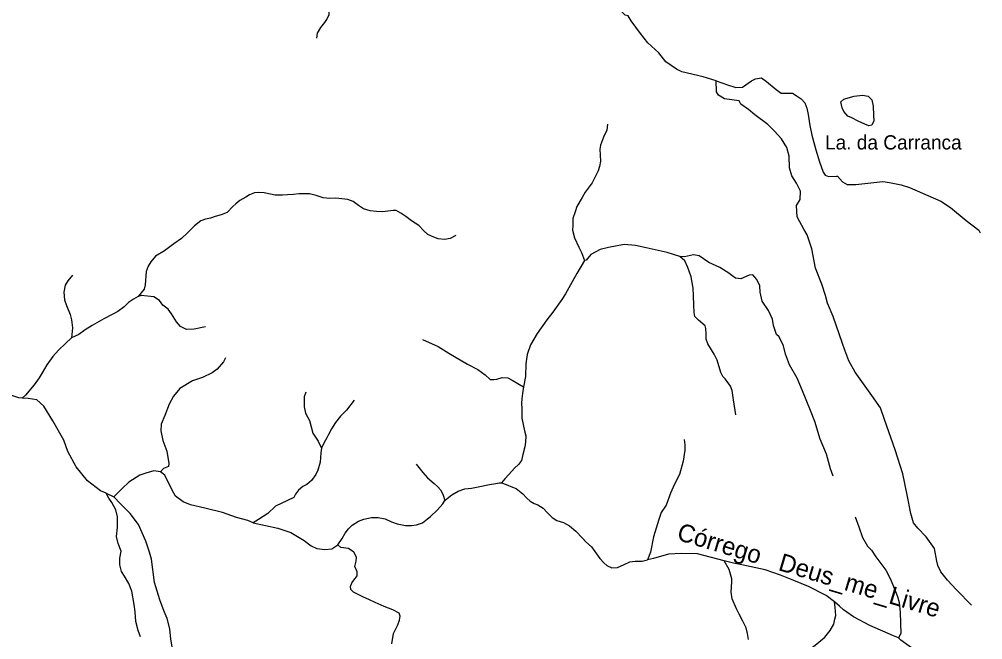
# Model space of a CAD drawing. Extents: x 717.8 to 772.7, y 8672.2 to 8728.
# Drawn here: x 761.61 to 772.42, y 8693.87 to 8700.84 of the extents above; entities that cross this region are included whole.
import ezdxf
from ezdxf.enums import TextEntityAlignment as Align

# ---------------------------------------------------------------- set-up
doc = ezdxf.new("R2010")
doc.units = 0
doc.header["$LTSCALE"] = 0.08
doc.linetypes.add('LONG_DASHED', pattern=[7.5, 6, -1.5])
doc.layers.add('3', color=7, linetype='LONG_DASHED', lineweight=25)
doc.layers.add('9', color=7, linetype='LONG_DASHED', lineweight=25)
doc.layers.add('61', color=7, linetype='Continuous')

msp = doc.modelspace()

# ---------------------------------------------------------------- linework, layer by layer
at = {"layer": '3'}
for points in [[(770.8462, 8699.8467), (770.829, 8699.9124), (770.8634, 8699.9428), (770.8867, 8699.9503)], [(770.8867, 8699.9503), (770.9788, 8699.9778), (771.0726, 8699.9883), (771.1373, 8699.9782), (771.1778, 8699.9367), (771.1938, 8699.8654), (771.1968, 8699.765), (771.1998, 8699.701), (771.1798, 8699.6515), (771.1443, 8699.6432), (771.1014, 8699.6614), (771.0245, 8699.6979), (770.954, 8699.7343), (770.9079, 8699.7526), (770.865, 8699.8042), (770.8462, 8699.8467)]]:
    msp.add_lwpolyline(points, dxfattribs=at)
at = {"layer": '9'}
msp.add_line((762.5827, 8695.5157), (762.6703, 8695.4765), dxfattribs=at)
for points in [[(764.9492, 8700.6283), (764.9568, 8700.6836), (764.9933, 8700.7489), (765.0358, 8700.8045), (765.0603, 8700.8374), (765.0866, 8700.8944), (765.0806, 8701.0439), (765.067, 8701.0857), (765.0496, 8701.173), (765.0526, 8701.2747), (765.0843, 8701.3926), (765.1202, 8701.4825), (765.1866, 8701.7016), (765.2041, 8701.7251)], [(769.4305, 8700.1491), (769.2842, 8700.1939), (769.0451, 8700.2496), (768.9852, 8700.279), (768.8659, 8700.3643), (768.7872, 8700.4645), (768.6633, 8700.5745), (768.5828, 8700.6794), (768.4757, 8700.8226), (768.4437, 8700.8809), (768.4086, 8700.8887), (768.3161, 8700.9848), (768.2855, 8701.014)], [(769.4305, 8700.1491), (769.5579, 8700.1036), (769.6531, 8700.0755), (769.7281, 8700.0798), (769.8284, 8700.1505), (769.8731, 8700.1736), (769.9408, 8700.1816), (769.9971, 8700.1426), (770.1024, 8700.0532), (770.1601, 8700.0121), (770.2858, 8700.0126), (770.3297, 8699.9852)], [(772.2973, 8694.2594), (772.13, 8694.4311), (772.0272, 8694.5392), (771.9522, 8694.6337), (771.919, 8694.703), (771.9082, 8694.7535), (771.8824, 8694.8934), (771.7892, 8695.0275), (771.6933, 8695.122), (771.6457, 8695.1833), (771.6153, 8695.2889), (771.576, 8695.4992), (771.5276, 8695.7351), (771.4394, 8696.0051), (771.3195, 8696.3431), (771.2741, 8696.4751), (771.1767, 8696.6157), (770.9899, 8696.8769), (770.9213, 8697.0039), (770.8745, 8697.1243), (770.8471, 8697.1964), (770.7434, 8697.5002), (770.6814, 8697.6496), (770.6576, 8697.7369), (770.618, 8697.8646), (770.5451, 8698.0456), (770.5055, 8698.2605), (770.4523, 8698.4193), (770.4162, 8698.4842), (770.3693, 8698.5636), (770.3398, 8698.6206), (770.3341, 8698.7469), (770.3723, 8698.8176), (770.3774, 8698.9106), (770.3341, 8698.9979), (770.2807, 8699.083), (770.2543, 8699.171), (770.2514, 8699.3023), (770.2248, 8699.4004), (770.1627, 8699.497), (770.0842, 8699.5857), (770.0106, 8699.6599), (769.8643, 8699.7689), (769.7929, 8699.8258), (769.709, 8699.8871), (769.6879, 8699.9243), (769.5232, 8699.9488), (769.4564, 8699.9877), (769.4353, 8700.024), (769.4305, 8700.1491)], [(770.3297, 8699.9852), (770.3845, 8699.9457), (770.4249, 8699.9023), (770.4502, 8699.8417), (770.4624, 8699.7724), (770.4828, 8699.6479), (770.5046, 8699.5389), (770.5513, 8699.3743)], [(768.2115, 8699.6608), (768.2024, 8699.5959), (768.1649, 8699.5164), (768.1323, 8699.4277), (768.1239, 8699.3822), (768.1323, 8699.2485), (768.1206, 8699.1881), (768.1051, 8699.1368), (768.0733, 8699.0699), (768.0371, 8699.0046), (767.9596, 8698.8984), (767.9252, 8698.8367), (767.8649, 8698.736), (767.8461, 8698.6763), (767.8206, 8698.6034), (767.8204, 8698.5223), (767.8161, 8698.471), (767.8407, 8698.3859), (767.8901, 8698.282), (767.9201, 8698.2206), (767.9528, 8698.1295)], [(770.5513, 8699.3743), (770.5903, 8699.2401), (770.6302, 8699.1242), (770.6525, 8699.0907), (770.6935, 8699.0748), (770.7802, 8699.08), (770.7931, 8699.0792), (770.8494, 8699.015), (770.9006, 8698.9833), (770.9979, 8698.9847), (771.3001, 8699.0201), (771.3754, 8699.0061), (771.5059, 8698.9825), (771.6026, 8698.9521), (771.9525, 8698.7968), (772.0603, 8698.727), (772.237, 8698.5818), (772.3809, 8698.4704), (772.3933, 8698.4434)], [(766.5089, 8698.4106), (766.4463, 8698.376), (766.3791, 8698.3676), (766.311, 8698.3742), (766.2624, 8698.3919), (766.1952, 8698.4246), (766.1486, 8698.4657), (766.0944, 8698.5236), (766.0105, 8698.5759), (765.9484, 8698.6237), (765.8925, 8698.6612), (765.8388, 8698.6908), (765.8033, 8698.6917), (765.7455, 8698.6861), (765.6849, 8698.6774), (765.6172, 8698.6821), (765.5473, 8698.6891), (765.4702, 8698.7124), (765.4169, 8698.7487), (765.3562, 8698.7926), (765.2942, 8698.8177), (765.2266, 8698.8248), (765.1612, 8698.8294), (765.0931, 8698.8291), (765.0194, 8698.8338), (764.942, 8698.8622), (764.865, 8698.8786), (764.7506, 8698.8795), (764.685, 8698.8741), (764.6198, 8698.8695), (764.563, 8698.8645), (764.4789, 8698.8665), (764.4277, 8698.8762), (764.3555, 8698.8927), (764.2948, 8698.895), (764.2481, 8698.8927), (764.1899, 8698.8669), (764.1502, 8698.8435), (764.0849, 8698.8061), (764.0382, 8698.7687), (764.0033, 8698.7383), (763.9404, 8698.6704), (763.8751, 8698.6447), (763.8075, 8698.6237), (763.7538, 8698.6073), (763.6979, 8698.5957), (763.6454, 8698.5746), (763.5746, 8698.5193), (763.499, 8698.4436), (763.4271, 8698.3783), (763.3412, 8698.3166), (763.2375, 8698.2379), (763.1349, 8698.1812), (763.0852, 8698.1156), (763.0543, 8698.0659), (763.0311, 8698.0088), (763.0264, 8697.9573), (763.0241, 8697.9058), (763.0218, 8697.8566), (763.0102, 8697.8098), (762.9437, 8697.7266)], [(769.0237, 8698.1752), (768.8804, 8698.2221), (768.6466, 8698.2723), (768.5246, 8698.2987), (768.3975, 8698.3113), (768.2202, 8698.2783), (768.1283, 8698.2548), (768.0248, 8698.1971), (767.9723, 8698.1359), (767.9528, 8698.1295)], [(770.7448, 8695.7086), (770.7131, 8695.7881), (770.6711, 8695.9537), (770.5986, 8696.122), (770.539, 8696.322), (770.4906, 8696.4435), (770.4003, 8696.6674), (770.3386, 8696.8102), (770.2553, 8696.9575), (770.2098, 8697.0779), (770.1849, 8697.1726), (770.1388, 8697.2738), (770.1087, 8697.2993), (770.0748, 8697.3989), (770.0624, 8697.4707), (770.0185, 8697.5686), (769.946, 8697.6743), (769.9234, 8697.7765), (769.9199, 8697.8464), (769.889, 8697.9189), (769.842, 8697.9683), (769.8011, 8697.9675), (769.7061, 8697.9251), (769.6467, 8697.9328), (769.6081, 8697.9621), (769.5744, 8697.9882), (769.4704, 8698.052), (769.3477, 8698.1098), (769.2392, 8698.1843), (769.1766, 8698.1931), (769.0745, 8698.1716), (769.0237, 8698.1752)], [(767.9528, 8698.1295), (767.8647, 8697.9862), (767.8125, 8697.8897), (767.7379, 8697.7561), (767.6978, 8697.6941), (767.5982, 8697.549), (767.5307, 8697.4643), (767.4227, 8697.3088), (767.3474, 8697.1825), (767.3105, 8697.075), (767.2933, 8696.9715), (767.29, 8696.8257), (767.2672, 8696.7098)], [(769.6513, 8696.3983), (769.6262, 8696.5653), (769.611, 8696.6712), (769.5913, 8696.7192), (769.5553, 8696.7716), (769.5307, 8696.8029), (769.5058, 8696.8291), (769.4814, 8696.872), (769.4434, 8697.0105), (769.4099, 8697.0783), (769.3369, 8697.196), (769.3181, 8697.2466), (769.3189, 8697.3085), (769.3146, 8697.3677), (769.3053, 8697.3982), (769.2323, 8697.4586), (769.1902, 8697.4999), (769.1833, 8697.5462), (769.1816, 8697.6278), (769.1773, 8697.7386), (769.173, 8697.8206), (769.1487, 8697.9489), (769.1143, 8698.0505), (769.0778, 8698.1285), (769.0237, 8698.1752)], [(762.2035, 8697.967), (762.1511, 8697.9032), (762.1229, 8697.8526), (762.1079, 8697.7757), (762.1132, 8697.6889), (762.1389, 8697.6256), (762.1785, 8697.5226), (762.1948, 8697.4641), (762.2065, 8697.3752), (762.1948, 8697.2628)], [(762.9437, 8697.7266), (762.8913, 8697.6953), (762.8329, 8697.6603), (762.784, 8697.6112), (762.7142, 8697.5567), (762.6496, 8697.5239), (762.5577, 8697.4735), (762.426, 8697.3988), (762.3467, 8697.3522), (762.2744, 8697.3008), (762.1948, 8697.2628)], [(763.6982, 8697.384), (763.5712, 8697.3587), (763.4835, 8697.3569), (763.4181, 8697.3886), (763.3733, 8697.4428), (763.3164, 8697.5296), (763.28, 8697.5829), (763.2202, 8697.6277), (763.1818, 8697.6795), (763.1163, 8697.722), (762.9753, 8697.7371), (762.9437, 8697.7266)], [(762.1948, 8697.2628), (762.1274, 8697.1982), (762.0481, 8697.1235), (761.9851, 8697.0533), (761.9174, 8696.9602), (761.8632, 8696.8668), (761.8315, 8696.8106), (761.7734, 8696.7347), (761.676, 8696.6184), (761.6383, 8696.5849)], [(766.1343, 8697.242), (766.3086, 8697.1636), (766.4301, 8697.0901), (766.6375, 8696.9643), (766.7554, 8696.9068), (766.8372, 8696.8445), (766.8947, 8696.7949), (766.9331, 8696.7929), (766.9665, 8696.7959), (767.0295, 8696.815), (767.0918, 8696.8105), (767.1409, 8696.7874), (767.2027, 8696.7486), (767.2672, 8696.7098)], [(763.921, 8697.0363), (763.9014, 8696.9915), (763.8298, 8696.9104), (763.7717, 8696.8698), (763.6643, 8696.8157), (763.5523, 8696.7786), (763.409, 8696.6931), (763.3401, 8696.6071), (763.2882, 8696.5183), (763.2426, 8696.391), (763.2004, 8696.2899), (763.1959, 8696.217), (763.217, 8696.1088), (763.2626, 8695.9887), (763.2855, 8695.8492), (763.2812, 8695.8153), (763.2279, 8695.7934), (763.1917, 8695.7552)], [(761.6383, 8696.5849), (761.6018, 8696.5876), (761.4904, 8696.6249), (761.4087, 8696.6621), (761.2158, 8696.6625), (761.1192, 8696.6849), (760.9494, 8696.7388), (760.9022, 8696.7484)], [(767.2672, 8696.7098), (767.2569, 8696.6348), (767.249, 8696.5779), (767.2465, 8696.5236), (767.249, 8696.4694), (767.249, 8696.4202), (767.2489, 8696.3607), (767.2654, 8696.2888), (767.2782, 8696.2157), (767.2941, 8696.1616), (767.2916, 8696.0891), (767.2838, 8696.0374), (767.2619, 8695.9495), (767.2438, 8695.8822), (767.2124, 8695.8368), (767.1678, 8695.7967), (767.1034, 8695.7268), (767.0597, 8695.6776), (767.0204, 8695.6324)], [(762.5827, 8695.5157), (762.5209, 8695.5421), (762.3748, 8695.6561), (762.2441, 8695.814), (762.1526, 8695.9848), (762.1066, 8696.1124), (761.9828, 8696.3302), (761.8844, 8696.4953), (761.8026, 8696.5655), (761.7057, 8696.58), (761.6383, 8696.5849)], [(764.8248, 8696.6496), (764.8062, 8696.5996), (764.804, 8696.4863), (764.821, 8696.4138), (764.8671, 8696.3319), (764.9045, 8696.1893), (764.9632, 8696.1004), (765, 8696.0208)], [(765.3684, 8696.5627), (765.2802, 8696.4508), (765.2129, 8696.3807), (765.1588, 8696.3122), (765.112, 8696.2408), (765.0779, 8696.1751), (765.0616, 8696.1376), (765.0288, 8696.085), (765, 8696.0208)], [(769.0697, 8696.1212), (769.0788, 8696.0585), (769.0789, 8695.9981), (769.062, 8695.8769), (769.0201, 8695.7256), (768.9613, 8695.6163), (768.9194, 8695.5154), (768.8675, 8695.3798), (768.8129, 8695.2999), (768.7853, 8695.221), (768.7268, 8695.0276), (768.6939, 8694.853), (768.6602, 8694.767)], [(765, 8696.0208), (764.9926, 8695.9691), (764.9862, 8695.8661), (764.958, 8695.7733), (764.9351, 8695.7249), (764.8891, 8695.6586), (764.8351, 8695.6134), (764.7919, 8695.5897), (764.7415, 8695.55), (764.7081, 8695.5041), (764.6896, 8695.4686), (764.6186, 8695.434), (764.4835, 8695.3716), (764.3964, 8695.2882), (764.2924, 8695.2192), (764.233, 8695.1823)], [(766.0634, 8695.8442), (766.136, 8695.7477), (766.1902, 8695.69), (766.2637, 8695.6239), (766.3051, 8695.5877), (766.3373, 8695.5532), (766.3606, 8695.5066), (766.3837, 8695.435)], [(763.1917, 8695.7552), (763.1187, 8695.7663), (763.0285, 8695.7408), (762.9602, 8695.7174), (762.8379, 8695.6385)], [(764.233, 8695.1823), (764.1746, 8695.208), (764.0474, 8695.2444), (763.8899, 8695.299), (763.6898, 8695.3483), (763.529, 8695.387), (763.4489, 8695.4175), (763.3623, 8695.4834), (763.3234, 8695.5504), (763.2429, 8695.7169), (763.1917, 8695.7552)], [(762.8379, 8695.6385), (762.7601, 8695.5641), (762.6703, 8695.4765)], [(766.3837, 8695.435), (766.4118, 8695.4553), (766.4638, 8695.499), (766.5356, 8695.5391), (766.6076, 8695.5661), (766.685, 8695.5738), (766.7576, 8695.5894), (766.8845, 8695.6142), (766.9589, 8695.6253), (766.9929, 8695.6324), (767.0204, 8695.6324)], [(767.0204, 8695.6324), (767.0726, 8695.6135), (767.1448, 8695.5851), (767.1864, 8695.5679), (767.2615, 8695.5101), (767.3029, 8695.4629), (767.341, 8695.425), (767.3867, 8695.4002), (767.4291, 8695.3853), (767.4884, 8695.3482), (767.5341, 8695.2976), (767.5905, 8695.2442), (767.6401, 8695.2085), (767.7162, 8695.1855), (767.7855, 8695.1498), (767.8568, 8695.0901), (767.929, 8695.0096), (767.9676, 8694.9711), (768.0302, 8694.9145), (768.1251, 8694.7837), (768.1703, 8694.7341), (768.2031, 8694.7022), (768.2609, 8694.6762), (768.3244, 8694.681), (768.3971, 8694.7151), (768.4627, 8694.7446), (768.52, 8694.7537), (768.6, 8694.7518), (768.6602, 8694.767)], [(762.9672, 8693.9006), (762.9407, 8693.9735), (762.9154, 8694.0754), (762.9093, 8694.1819), (762.8984, 8694.2645), (762.8712, 8694.4169), (762.8385, 8694.5008), (762.7876, 8694.5823), (762.7561, 8694.637), (762.735, 8694.7119), (762.7367, 8694.7858), (762.7492, 8694.863), (762.719, 8694.9503), (762.6978, 8695.0303), (762.7086, 8695.1362), (762.7103, 8695.2495), (762.69, 8695.329), (762.6468, 8695.4127), (762.6113, 8695.4618), (762.5827, 8695.5157)], [(763.3248, 8693.7917), (763.3081, 8693.8752), (763.2957, 8693.993), (763.2668, 8694.1079), (763.234, 8694.1876), (763.1865, 8694.3198), (763.1266, 8694.5109), (763.0905, 8694.7741), (763.0701, 8694.8529), (763.0284, 8694.9772), (762.9453, 8695.164), (762.8514, 8695.2867), (762.7437, 8695.3978), (762.6703, 8695.4765)], [(765.1848, 8694.937), (765.232, 8695.0068), (765.2663, 8695.0677), (765.3016, 8695.1153), (765.346, 8695.1586), (765.4154, 8695.2003), (765.4771, 8695.2239), (765.5622, 8695.2447), (765.6371, 8695.2422), (765.7144, 8695.2267), (765.7867, 8695.1958), (765.8513, 8695.1726), (765.9442, 8695.1545), (766.0114, 8695.152), (766.0681, 8695.1599), (766.1326, 8695.1832), (766.1918, 8695.2271), (766.2234, 8695.2539), (766.3033, 8695.3303), (766.3612, 8695.3974), (766.3837, 8695.435)], [(764.233, 8695.1823), (764.5104, 8695.1223), (764.6558, 8695.076), (764.8068, 8694.9853), (764.8837, 8694.925), (764.9486, 8694.8954), (765.0393, 8694.8824), (765.1144, 8694.8917), (765.1848, 8694.937)], [(770.9902, 8695.2495), (771.0332, 8695.1384), (771.0747, 8695.0192), (771.1289, 8694.9219), (771.1746, 8694.8763), (771.2227, 8694.8002), (771.3345, 8694.65), (771.3881, 8694.5514), (771.4304, 8694.4501), (771.4674, 8694.3541), (771.4853, 8694.2893), (771.4965, 8694.1754), (771.503, 8693.9387), (771.4783, 8693.8903)], [(765.7901, 8693.8225), (765.8094, 8693.9386), (765.8307, 8693.9857), (765.8561, 8694.0371), (765.8746, 8694.0904), (765.883, 8694.1342), (765.8701, 8694.1678), (765.7994, 8694.2054), (765.7023, 8694.2425), (765.6011, 8694.2883), (765.5377, 8694.3187), (765.4659, 8694.3534), (765.4104, 8694.3775), (765.3599, 8694.4045), (765.3291, 8694.4359), (765.3247, 8694.4683), (765.3399, 8694.5104), (765.3774, 8694.557), (765.3999, 8694.589), (765.401, 8694.6322), (765.3735, 8694.6911), (765.3874, 8694.7517), (765.3917, 8694.7957), (765.3643, 8694.8534), (765.3023, 8694.893), (765.217, 8694.9077), (765.1848, 8694.937)], [(769.5198, 8694.7559), (769.221, 8694.8356), (769.0423, 8694.8404), (768.8959, 8694.8322), (768.7267, 8694.7807), (768.6602, 8694.767)], [(769.7929, 8693.8715), (769.7813, 8693.9413), (769.7673, 8694.0029), (769.7283, 8694.0784), (769.6886, 8694.1571), (769.6595, 8694.2174), (769.6108, 8694.3284), (769.6004, 8694.4058), (769.6051, 8694.5196), (769.605, 8694.5542), (769.5757, 8694.6573), (769.5198, 8694.7559)], [(770.7572, 8694.2945), (770.6641, 8694.365), (770.4669, 8694.4675), (770.3028, 8694.5344), (770.152, 8694.5953), (769.9814, 8694.6542), (769.7181, 8694.7104), (769.6269, 8694.7303), (769.5198, 8694.7559)], [(770.7866, 8693.1056), (770.7046, 8693.1566), (770.6563, 8693.2042), (770.6332, 8693.2472), (770.5968, 8693.3432), (770.5583, 8693.4108), (770.5139, 8693.4675), (770.4934, 8693.531), (770.4795, 8693.6309), (770.481, 8693.6379), (770.4802, 8693.719), (770.4934, 8693.7712), (770.5608, 8693.8236), (770.6507, 8693.8997), (770.7089, 8693.9744), (770.7506, 8694.0433), (770.7645, 8694.1002), (770.7738, 8694.1432), (770.7672, 8694.2332), (770.7572, 8694.2945)], [(771.4783, 8693.8903), (771.4222, 8693.9135), (771.1541, 8694.0281), (770.9714, 8694.1281), (770.8591, 8694.2041), (770.8164, 8694.2465), (770.7572, 8694.2945)], [(772.4231, 8692.7582), (772.3686, 8692.8108), (772.2997, 8692.8775), (772.2046, 8692.9499), (772.1338, 8692.9982), (772.0389, 8693.0997), (772.0009, 8693.1511), (771.9619, 8693.2292), (771.9262, 8693.2939), (771.8739, 8693.3923), (771.8299, 8693.5545), (771.8034, 8693.6141), (771.7538, 8693.6778), (771.6602, 8693.7533), (771.5958, 8693.7967), (771.5023, 8693.8651), (771.4783, 8693.8903)]]:
    msp.add_lwpolyline(points, dxfattribs=at)

# ---------------------------------------------------------------- texts
at = {"layer": '61'}
msp.add_text('La. da Carranca', height=0.16, dxfattribs=at).set_placement((770.6524, 8699.3779))
msp.add_text('Córrego   Deus_me_Livre', height=0.2, rotation=343.293, dxfattribs=at).set_placement((770.4448, 8694.5556), align=Align.CENTER)

doc.saveas('drawing.dxf')
